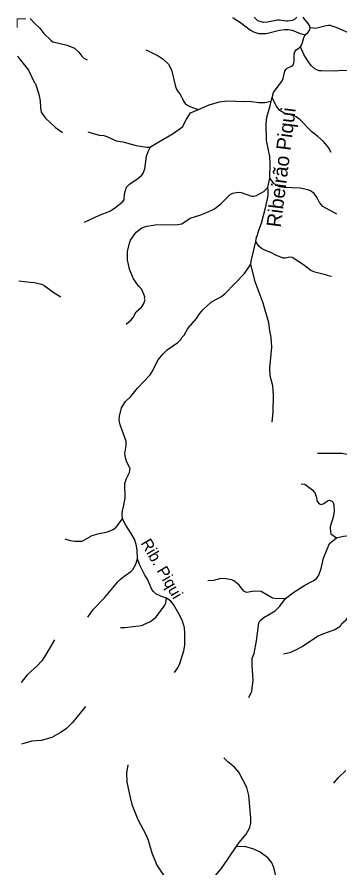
# Model space of a CAD drawing. Extents: x 280.4 to 335.6, y 8893.9 to 8949.5.
# Drawn here: x 280.43 to 284.9, y 8937.49 to 8949.25 of the extents above; entities that cross this region are included whole.
import ezdxf
from ezdxf.enums import TextEntityAlignment as Align

# ---------------------------------------------------------------- set-up
doc = ezdxf.new("R2010")
doc.units = 0
doc.header["$LTSCALE"] = 0.064
doc.linetypes.add('LONG_DASHED', pattern=[7.5, 6, -1.5])
doc.layers.add('61', color=7, linetype='Continuous')
for name, color, linetype, lineweight in [('63', 7, 'Continuous', 13), ('7', 7, 'Continuous', 25), ('9', 7, 'LONG_DASHED', 25)]:
    doc.layers.add(name, color=color, linetype=linetype, lineweight=lineweight)

msp = doc.modelspace()

# ---------------------------------------------------------------- linework, layer by layer
at = {"layer": '63'}
msp.add_lwpolyline([(280.5572, 8949.2312), (280.434, 8949.2312), (280.434, 8949.1098)], dxfattribs=at)
at = {"layer": '7'}
msp.add_line((283.905, 8946.8953), (283.9301, 8947.0276), dxfattribs=at)
for points in [[(284.3071, 8949.2542), (284.293, 8949.2396), (284.2737, 8949.2222), (284.2415, 8949.2051), (284.2074, 8949.2001), (284.1778, 8949.1965), (284.1519, 8949.1973), (284.0641, 8949.2094), (284.0367, 8949.2099), (284.0133, 8949.2079), (283.8978, 8949.1819), (283.8425, 8949.178), (283.7641, 8949.2005), (283.7257, 8949.2437), (283.7194, 8949.2508)], [(284.4891, 8949.1063), (284.4796, 8949.1378), (284.4646, 8949.1658), (284.3958, 8949.2441), (284.3875, 8949.2547)], [(285.3095, 8948.7989), (285.1821, 8948.9227), (285.0213, 8949.0348), (284.8635, 8949.1064), (284.7955, 8949.13), (284.7718, 8949.1353), (284.7428, 8949.1365), (284.7126, 8949.1344), (284.5835, 8949.1017), (284.5612, 8949.0979), (284.5255, 8949.1014), (284.4891, 8949.1063)], [(284.4202, 8949.0073), (284.4576, 8949.0396), (284.4752, 8949.0635), (284.4855, 8949.0883), (284.4891, 8949.1063)], [(284.3548, 8948.8429), (284.3716, 8948.8643), (284.3864, 8948.9009), (284.3959, 8948.9541), (284.4026, 8948.9728), (284.4202, 8949.0073)], [(283.9625, 8948.1408), (283.9845, 8948.2108), (284.1017, 8948.3744), (284.117, 8948.403), (284.1416, 8948.5038), (284.1526, 8948.5299), (284.1726, 8948.5452), (284.2317, 8948.5733), (284.254, 8948.593), (284.2656, 8948.6214), (284.2709, 8948.6455), (284.2695, 8948.7403), (284.2785, 8948.7751), (284.2939, 8948.7978), (284.3548, 8948.8429)], [(285.2872, 8948.5562), (285.1729, 8948.5192), (285.0936, 8948.5096), (284.9373, 8948.5144), (284.8358, 8948.5049), (284.6484, 8948.5096), (284.6157, 8948.5116), (284.5823, 8948.5222), (284.5537, 8948.5387), (284.5105, 8948.5819), (284.4628, 8948.6394), (284.4045, 8948.7384), (284.3548, 8948.8429)], [(283.9301, 8947.0276), (283.9383, 8947.2269), (283.9314, 8947.3258), (283.8855, 8947.5476), (283.8824, 8947.7724), (283.891, 8947.8695), (283.9381, 8948.0259), (283.9508, 8948.0892)], [(283.9508, 8948.0892), (283.9586, 8948.1283), (283.9625, 8948.1408)], [(284.7805, 8947.3834), (284.7439, 8947.4512), (284.6766, 8947.5345), (284.5967, 8947.6032), (284.5167, 8947.6611), (284.3466, 8947.8374), (284.2976, 8947.8754), (284.2658, 8947.8916), (284.1303, 8947.9242), (284.0705, 8947.9632), (284.0187, 8948.0253), (283.9625, 8948.1408)], [(284.8582, 8946.5278), (284.6638, 8946.6341), (284.6182, 8946.6881), (284.5881, 8946.755), (284.546, 8946.8143), (284.4959, 8946.8498), (284.4573, 8946.8657), (284.3535, 8946.8879), (284.1327, 8946.8992), (284.0647, 8946.9084), (283.9931, 8946.9455), (283.9301, 8947.0276)], [(281.9427, 8945.0077), (282.0128, 8945.0648), (282.0429, 8945.1005), (282.0836, 8945.177), (282.1584, 8945.2427), (282.1848, 8945.2841), (282.2063, 8945.3443), (282.2001, 8945.3615), (282.2013, 8945.3845), (282.1617, 8945.4878), (282.1265, 8945.5278), (282.1179, 8945.5295), (282.0683, 8945.6004), (282.044, 8945.6351), (281.9905, 8945.7668), (281.965, 8945.8946), (281.9648, 8946.0108), (281.9907, 8946.1274), (282.0058, 8946.1666), (282.0836, 8946.2789), (282.1606, 8946.338), (282.2298, 8946.3632), (282.3455, 8946.3793), (282.6525, 8946.3842), (282.7138, 8946.3961), (282.8316, 8946.4728), (282.9787, 8946.5169), (283.0703, 8946.558), (283.1668, 8946.6013), (283.2602, 8946.6753), (283.3835, 8946.7986), (283.4202, 8946.819), (283.4962, 8946.8318), (283.5346, 8946.8272), (283.6768, 8946.7776), (283.7119, 8946.7778), (283.7464, 8946.7872), (283.8471, 8946.8416), (283.905, 8946.8953)], [(283.738, 8946.1488), (283.7478, 8946.2123), (283.759, 8946.2251), (283.7795, 8946.3073), (283.8149, 8946.4042), (283.8822, 8946.6537), (283.9079, 8946.7887), (283.911, 8946.8535), (283.905, 8946.8953)], [(283.6686, 8945.839), (283.6728, 8945.8791), (283.738, 8946.1487), (283.738, 8946.1488)], [(284.7835, 8945.6648), (284.7377, 8945.6769), (284.7219, 8945.6868), (284.5562, 8945.7254), (284.4977, 8945.7511), (284.3958, 8945.8287), (284.2434, 8945.931), (284.2102, 8945.9315), (284.1458, 8945.919), (284.1171, 8945.922), (284.0143, 8945.9607), (283.9479, 8945.9987), (283.8728, 8946.0266), (283.8165, 8946.0555), (283.7795, 8946.0858), (283.738, 8946.1488)], [(281.8949, 8942.315), (281.8887, 8942.3686), (281.8915, 8942.4395), (281.9007, 8942.4573), (281.9328, 8942.6027), (281.9267, 8942.8033), (281.9489, 8942.8705), (281.9906, 8942.9576), (281.9998, 8943.0089), (281.9521, 8943.1009), (281.9331, 8943.1577), (281.9266, 8943.2176), (281.9455, 8943.3304), (281.9422, 8943.3894), (281.8604, 8943.6147), (281.8497, 8943.6774), (281.8502, 8943.7369), (281.8798, 8943.8486), (281.9345, 8943.9356), (282.0091, 8944.0072), (282.1003, 8944.1242), (282.2766, 8944.3068), (282.3009, 8944.3426), (282.3867, 8944.514), (282.4553, 8944.5985), (282.5094, 8944.6541), (282.6605, 8944.7546), (282.7009, 8944.7933), (282.7213, 8944.828), (282.7451, 8944.8537), (282.7996, 8944.9464), (282.9184, 8945.0842), (282.9584, 8945.1517), (283.0054, 8945.2065), (283.1261, 8945.3165), (283.2636, 8945.3886), (283.3125, 8945.4289), (283.5805, 8945.7082), (283.6686, 8945.839)], [(283.9653, 8943.6541), (283.9799, 8943.7942), (283.9846, 8944.0195), (283.9734, 8944.1531), (283.9375, 8944.2929), (283.9304, 8944.3987), (283.9606, 8944.6905), (283.9511, 8944.8241), (283.9321, 8944.9144), (283.9191, 8945.0263), (283.8415, 8945.2974), (283.7291, 8945.5918), (283.6686, 8945.839)], [(280.4599, 8945.6043), (280.6182, 8945.5869), (280.6702, 8945.5812), (280.7765, 8945.5598), (280.8108, 8945.5441), (280.9503, 8945.4394), (281.0421, 8945.3831)], [(281.0969, 8942.0365), (281.1699, 8942.0146), (281.2341, 8942.0039), (281.334, 8942.0071), (281.4754, 8942.0853), (281.57, 8942.1138), (281.6879, 8942.137), (281.7627, 8942.1682), (281.8074, 8942.2014), (281.8949, 8942.315)], [(282.1021, 8941.7626), (282.0951, 8941.8874), (282.0832, 8941.9583), (282.0593, 8942.035), (282.0156, 8942.1132), (281.9397, 8942.227), (281.8949, 8942.315)], [(281.4162, 8940.9569), (281.4899, 8941.0633), (281.6464, 8941.2234), (281.8276, 8941.4424), (281.8679, 8941.4786), (281.9114, 8941.5154), (282.0111, 8941.5848), (282.0347, 8941.6135), (282.0797, 8941.688), (282.1021, 8941.7626)], [(282.5027, 8941.2178), (282.4322, 8941.2424), (282.3565, 8941.2783), (282.3206, 8941.3093), (282.3015, 8941.3367), (282.2399, 8941.4792), (282.202, 8941.5362), (282.1309, 8941.6816), (282.1021, 8941.7626)], [(281.8639, 8940.8142), (281.9262, 8940.8104), (282.1574, 8940.8414), (282.2699, 8940.8915), (282.3246, 8940.9278), (282.3607, 8940.9603), (282.4764, 8941.1099), (282.4923, 8941.1532), (282.5027, 8941.2178)], [(282.6144, 8940.1916), (282.6591, 8940.2536), (282.6802, 8940.3003), (282.7402, 8940.4902), (282.7548, 8940.5683), (282.758, 8940.6437), (282.7569, 8940.7359), (282.7515, 8940.8068), (282.7467, 8940.8278), (282.7388, 8940.8555), (282.7175, 8940.9144), (282.6694, 8941.0121), (282.5986, 8941.1306), (282.561, 8941.177), (282.5027, 8941.2178)], [(280.9529, 8940.6435), (280.8296, 8940.4276), (280.7753, 8940.3507), (280.7137, 8940.2824), (280.5736, 8940.1598), (280.4921, 8940.0502)], [(281.3812, 8939.7192), (281.203, 8939.4988), (281.1172, 8939.4146), (281.0458, 8939.3629), (280.9167, 8939.2912), (280.767, 8939.248), (280.6406, 8939.2402), (280.497, 8939.2008)], [(283.4685, 8937.7801), (283.5094, 8937.8403), (283.6067, 8937.9531), (283.6507, 8938.0383), (283.6538, 8938.0497), (283.6693, 8938.1062), (283.6712, 8938.1783), (283.6399, 8938.4901), (283.6122, 8938.5998), (283.5044, 8938.8122), (283.4431, 8938.8799), (283.353, 8938.9556), (283.2971, 8939.0116)], [(281.967, 8938.9139), (281.9473, 8938.7988), (281.9521, 8938.6717), (282.0016, 8938.4595), (282.0238, 8938.3645), (282.1057, 8938.1592), (282.2165, 8937.9498), (282.2476, 8937.8705), (282.2972, 8937.696), (282.3705, 8937.5274), (282.4689, 8937.3717), (282.5597, 8937.2125), (282.6042, 8937.1171), (282.6197, 8937.0564)], [(282.6197, 8937.0564), (282.6415, 8937.0718), (282.6624, 8937.0855), (282.7939, 8937.1632), (283.0361, 8937.2893), (283.1847, 8937.388), (283.2726, 8937.4919), (283.4685, 8937.7801)], [(284.0697, 8937.1445), (283.9876, 8937.4914), (283.9543, 8937.5674), (283.9063, 8937.628), (283.7976, 8937.7038), (283.711, 8937.7472), (283.5872, 8937.7831), (283.4685, 8937.7801)]]:
    msp.add_lwpolyline(points, dxfattribs=at)
at = {"layer": '9'}
for points in [[(283.4141, 8949.2491), (283.4254, 8949.2419), (283.5266, 8949.1772), (283.6654, 8949.0726), (283.7047, 8949.0504), (283.7788, 8949.0249), (283.88, 8949.0248), (284.0672, 8949.0724), (284.1353, 8949.082), (284.1878, 8949.0806), (284.2405, 8949.0721), (284.3514, 8949.0255), (284.4202, 8949.0073)], [(280.614, 8949.2331), (280.6735, 8949.1749), (280.7502, 8949.0998), (280.807, 8949.0286), (280.9027, 8948.9329), (280.9317, 8948.9124), (281.1288, 8948.8676), (281.23, 8948.8233), (281.2915, 8948.7669), (281.3303, 8948.7113), (281.3568, 8948.6845), (281.4035, 8948.6616)], [(282.2181, 8948.7991), (282.2506, 8948.7891), (282.387, 8948.719), (282.4584, 8948.6699), (282.5287, 8948.6044), (282.57, 8948.5266), (282.624, 8948.3137), (282.6329, 8948.2811), (282.646, 8948.2496), (282.6628, 8948.2213), (282.6863, 8948.1942), (282.7106, 8948.1507), (282.723, 8948.1218), (282.7393, 8948.0909), (282.7609, 8948.061), (282.7838, 8948.0412), (282.8243, 8948.018), (282.8777, 8947.998), (282.945, 8947.978)], [(280.4418, 8948.7199), (280.4523, 8948.7016), (280.5909, 8948.5207), (280.6775, 8948.3446), (280.6887, 8948.3327), (280.7368, 8948.189), (280.7554, 8948.0953), (280.7589, 8947.9986), (280.7697, 8947.9401), (280.8276, 8947.8541), (280.9647, 8947.7249), (281.0613, 8947.6572)], [(282.945, 8947.978), (283.0939, 8948.0425), (283.2357, 8948.0824), (283.345, 8948.0937), (283.5767, 8948.0874), (283.6448, 8948.092), (283.7791, 8948.0746), (283.864, 8948.073), (283.9508, 8948.0892)], [(282.2819, 8947.4572), (282.3943, 8947.529), (282.5959, 8947.644), (282.7232, 8947.7346), (282.7749, 8947.8349), (282.8326, 8947.9293), (282.945, 8947.978)], [(281.4159, 8947.6662), (281.5726, 8947.6193), (281.6342, 8947.6151), (281.678, 8947.6034), (281.8038, 8947.5432), (281.8975, 8947.5292), (282.0835, 8947.4761), (282.2303, 8947.4559), (282.26, 8947.4566), (282.2819, 8947.4572)], [(281.3672, 8946.4191), (281.574, 8946.5134), (281.7185, 8946.5713), (281.7827, 8946.6094), (281.8911, 8946.6929), (281.9149, 8946.7266), (281.9198, 8946.8117), (281.9485, 8946.9034), (281.9898, 8946.9429), (282.106, 8947.0195), (282.1589, 8947.0676), (282.181, 8947.0967), (282.203, 8947.1534), (282.2242, 8947.3283), (282.2474, 8947.3968), (282.2736, 8947.4427), (282.2819, 8947.4572)], [(284.5933, 8943.2242), (284.9327, 8943.2252), (285.0486, 8943.2013), (285.164, 8943.1642), (285.274, 8943.1049), (285.4029, 8943.0526), (285.5325, 8943.0328), (285.6597, 8943.0335), (285.7665, 8943.0441), (285.8544, 8943.1149), (285.9559, 8943.2728), (286.0215, 8943.3419), (286.1648, 8943.3695), (286.1659, 8943.3695)], [(284.368, 8942.8004), (284.4152, 8942.7926), (284.5256, 8942.7126), (284.5583, 8942.6675), (284.5775, 8942.6101), (284.5843, 8942.5642), (284.6134, 8942.5236), (284.647, 8942.5144), (284.6796, 8942.528), (284.7281, 8942.5617), (284.7572, 8942.5715), (284.7839, 8942.5649), (284.8078, 8942.5409), (284.8193, 8942.51), (284.8224, 8942.4155), (284.8099, 8942.3398), (284.7687, 8942.2037), (284.7712, 8942.1251), (284.7783, 8942.1094), (284.8537, 8942.0502)], [(284.1233, 8940.4486), (284.2208, 8940.4731), (284.3112, 8940.5119), (284.3798, 8940.5496), (284.5925, 8940.6904), (284.6643, 8940.7243), (284.8233, 8940.7807), (284.9003, 8940.8244), (284.9167, 8940.8396), (284.9242, 8940.8609), (284.9885, 8940.9159), (285.1286, 8941.1116), (285.2908, 8941.2948), (285.6612, 8941.5759), (285.7178, 8941.6546), (285.8371, 8941.8925), (285.9953, 8942.1346)], [(284.8537, 8942.0502), (284.9521, 8942.0744), (285.1672, 8942.098), (285.5582, 8942.1034), (285.7775, 8942.1271), (285.9953, 8942.1346)], [(284.1491, 8941.2134), (284.2635, 8941.303), (284.4155, 8941.3997), (284.5322, 8941.4557), (284.5794, 8941.4883), (284.6112, 8941.5377), (284.6438, 8941.6295), (284.6739, 8941.772), (284.7559, 8941.9756), (284.8532, 8942.0501), (284.8537, 8942.0502)], [(284.1491, 8941.2134), (284.0296, 8941.2096), (283.9687, 8941.2198), (283.811, 8941.3112), (283.7199, 8941.3129), (283.6098, 8941.2944), (283.5738, 8941.3163), (283.5093, 8941.3966), (283.4443, 8941.4552), (283.4074, 8941.471), (283.3226, 8941.487), (283.2521, 8941.4918), (283.1534, 8941.4632), (283.0751, 8941.4559)], [(283.643, 8939.8463), (283.6823, 8939.9314), (283.7028, 8940.0817), (283.6856, 8940.2935), (283.6858, 8940.3897), (283.7145, 8940.4523), (283.7471, 8940.6269), (283.7817, 8940.8772), (283.793, 8940.9049), (283.8492, 8940.9501), (284.0081, 8941.0443), (284.0714, 8941.1057), (284.1491, 8941.2134)], [(284.8187, 8938.6574), (284.8772, 8938.7313), (284.9816, 8938.8361)]]:
    msp.add_lwpolyline(points, dxfattribs=at)

# ---------------------------------------------------------------- texts
at = {"layer": '61'}
for s, height, rotation, p in [('Ribeirão Piqui', 0.2, 82.801, (284.1873, 8947.1636)), ('Rib. Piqui', 0.16, 300.256, (282.3705, 8941.5854))]:
    msp.add_text(s, height=height, rotation=rotation, dxfattribs=at).set_placement(p, align=Align.CENTER)

doc.saveas('drawing.dxf')
